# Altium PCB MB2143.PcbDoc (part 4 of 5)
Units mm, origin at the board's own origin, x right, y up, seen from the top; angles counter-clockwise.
Board outline 70 x 70 mm, 4 copper layers (Top Layer, Signal Layer 1, Signal Layer 2, Bottom Layer), stack 1.56 mm thick; 272 components, 188 nets, 1083 pads, 1158 vias.
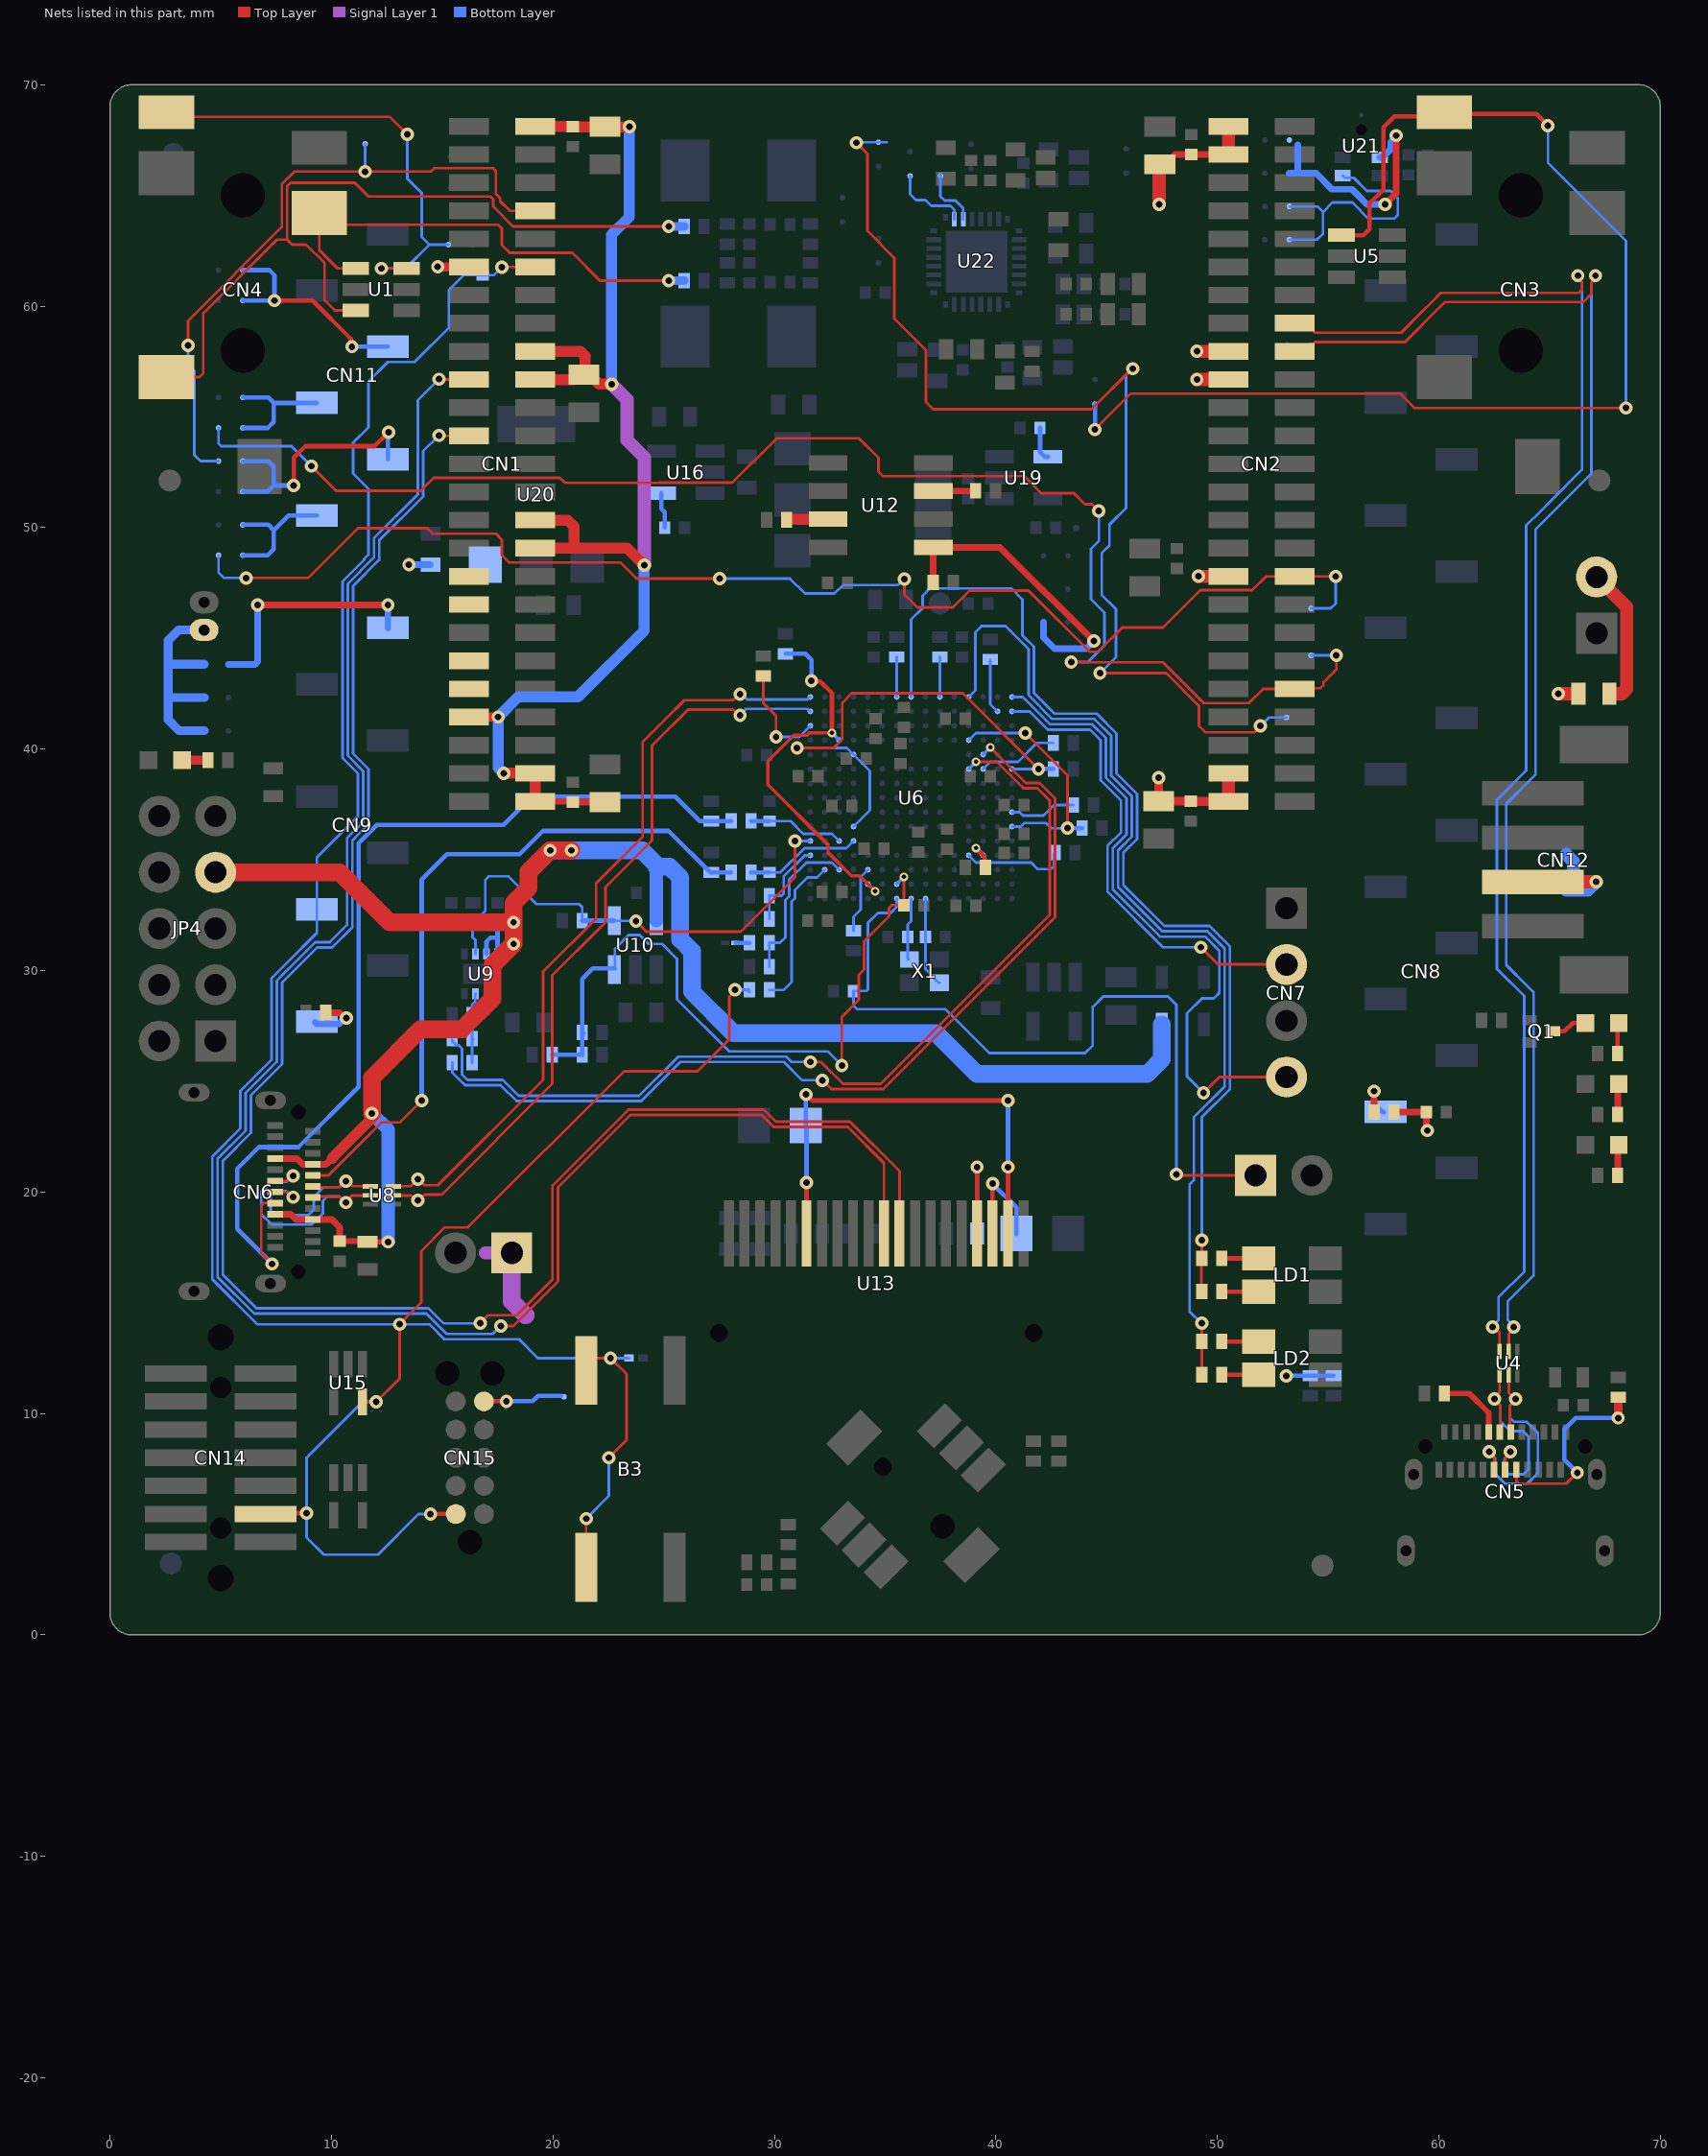
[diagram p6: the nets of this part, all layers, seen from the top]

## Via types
v1: diameter 0.6, hole 0.3, Top Layer to Bottom Layer, 1107 vias
v2: diameter 0.4, hole 0.2, Top Layer to Bottom Layer, tented both sides, 50 vias
v3: diameter 0.6, hole 0.3, Top Layer to Bottom Layer, tented both sides, 1 vias

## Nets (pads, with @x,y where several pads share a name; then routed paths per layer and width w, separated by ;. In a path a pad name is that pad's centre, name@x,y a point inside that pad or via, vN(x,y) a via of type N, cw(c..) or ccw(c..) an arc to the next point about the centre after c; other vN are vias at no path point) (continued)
NetC73_1: C73.1 U13.6 U13.19 | length 21.5
  Top Layer w0.2: v1(31.425,24.4) 31.444,24.4 31.719,24.125 v1(40.55,24.125) ; U13.6@31.45,18.125 v1(31.45,20.425) ; U13.19@40.55,18.125 v1(40.55,21.125)
  Bottom Layer w0.2: C73.1@31.425,23 v1(31.425,24.4) ; v1(31.45,20.425) C73.1@31.45,22.95 ; v1(40.55,21.125) v1(40.55,24.125)
NetC76_1: C76.1 U13.18 | length 5
  Top Layer w0.2: U13.18@39.85,18.125 v1(39.85,20.375)
  Bottom Layer w0.2: v1(39.85,20.375) 40.925,19.3 C76.1@40.925,18.125 C76.1@40.925,18.1
NetC79_1: C79.1 U16.4 | length 1.6
  Bottom Layer w0.2: U16.4@24.9,51.55 24.9,50.85 25.05,50.7 C79.1@25.05,50
NetC82_2: C82.2 U19.4 | length 1.5
  Bottom Layer w0.2: C82.2@42,54.506 42,53.4 42.2,53.2 U19.4@42.35,53.2
NetCN3_2: CN3.2 SB7.1 U5.1 | length 54.5
  Top Layer w0.12: v1(44.475,54.425) 46.1,56.05 58.25,56.05 58.9,55.4 v1(68.45,55.4)
  Top Layer w0.2: U5.1@55.6,63.2 56.6,63.2 56.875,63.475 56.875,64.635 57.5,65.26 57.5,68.075 57.999,68.574 60.074,68.574 CN3.2@60.25,68.75 60.326,68.674 64.401,68.674 v1(64.925,68.15)
  Bottom Layer w0.12: v1(64.925,68.15) 64.925,66.475 68.45,62.95 v1(68.45,55.4)
  Bottom Layer w0.2: v1(44.475,54.425) SB7.1@44.475,55.575
NetCN4_2: CN4.2 SB6.2 U1.6 | length 21.3
  Top Layer w0.12: CN4.2@2.55,68.75 2.75,68.55 12.625,68.55 v1(13.425,67.75) ; v1(12.25,61.7) U1.6@13.4,61.7
  Bottom Layer w0.12: v1(12.25,61.7) 13.35,61.7 14.425,62.775 ; v1(13.425,67.75) 13.425,65.75 14.075,65.1 14.075,63.125 14.425,62.775 ; SB6.2@15.275,62.775 14.425,62.775
NetCN4_4: CN4.4 R53.1 U1.1 | length 22
  Top Layer w0.12: U1.1@11.27,61.7 U1.1@11.1,61.7 10.275,61.7 9.45,62.525 CN4.4@9.45,64.2 9.975,63.675 17.525,63.675 17.7,63.5 17.7,62.75 18.05,62.4 20.875,62.4 22.125,61.15 v1(25.225,61.15)
  Bottom Layer w0.4: v1(25.225,61.15) R53.1@25.925,61.15
NetCN4_6: CN4.6 R45.1 U1.3 | length 36.4
  Top Layer w0.12: CN4.6@2.55,56.8 4.05,56.8 4.213,56.963 4.213,59.681 7.532,63 8,63 ; U1.3@11.1,59.8 10.15,59.8 9.693,60.257 9.693,61.943 8.86,62.776 8.224,62.776 8,63 ; v1(25.225,63.6) 18.2,63.6 17.3,64.5 17.3,64.825 17.175,64.95 11.675,64.95 11.055,65.57 8.163,65.57 8,65.408 8,63
  Bottom Layer w0.4: v1(25.225,63.6) R45.1@25.925,63.6
NetCN5_A5: CN5.A5 R6.2 | length 3.2
  Top Layer w0.25: R6.2@60.25,10.9 61.375,10.9 62.25,10.025 CN5.A5@62.25,9.16
NetCN5_B5: CN5.B5 R7.2 | length 9
  Top Layer w0.12: CN5.B5@63.5,7.46 63.5,6.94 63.61,6.83 65.755,6.83 v1(66.25,7.325)
  Top Layer w0.25: v1(68.095,9.795) v1@68.1,9.8
  Top Layer w0.4: v1@68.1,9.8 R7.2@68.1,10.725
  Bottom Layer w0.2: v1(66.25,7.325) 65.663,7.912 65.663,9.273 66.185,9.795 v1@67.845,9.795
NetCN6_A5: CN6.A5 R11.1 R13.2 | length 31.9
  Top Layer w0.12: CN6.A5@9.16,20.75 9.863,20.75 11.444,22.331 12.25,23.138 13.087,23.138 v1(14.075,24.125)
  Bottom Layer w0.2: v1(14.075,24.125) 14.075,34.1 15.22,35.245 18.495,35.245 19.55,36.3 25.223,36.3 R11.1@27.122,34.402 ; R11.1@27.15,34.43 R13.2@28.05,34.43
NetCN6_B5: CN6.B5 R14.2 R15.1 | length 44.6
  Top Layer w0.12: v1(7.325,16.75) 6.83,17.245 6.83,19.39 6.94,19.5 CN6.B5@7.46,19.5
  Bottom Layer w0.2: v1(7.325,16.75) 5.75,18.325 5.75,21.05 6.725,22.025 8.51,22.025 11.225,24.74 11.225,35.757 12.043,36.575 17.775,36.575 19.05,37.85 25.525,37.85 26.625,36.75 R14.2@28.05,36.75
NetCN8_8: CN8.8 R44.1 | length 2.1
  Top Layer w0.3: R44.1@57.075,23.602 v1(57.075,24.55)
  Bottom Layer w0.2: v1(57.075,24.55) 57.075,24.012 57.485,23.602 CN8.8@57.525,23.602
NetCN9_1: CN9.1 R43.1 | length 2.6
  Top Layer w0.3: R43.1@9.75,28.1 10.365,28.1 10.615,27.85 v1(10.675,27.85)
  Bottom Layer w0.3: CN9.1@9.267,27.666 9.35,27.583 10.329,27.583 10.571,27.825 v1@10.65,27.825 ; CN9.1@9.825,27.675 CN9.1@9.85,27.65
NetCN11_1: CN11.1 SB5.1 SB10.1 | length 6.1
  Bottom Layer w0.2: SB5.1@6,48.75 7.125,48.75 7.398,49.023 7.398,49.877 ; SB10.1@6,50.125 7.15,50.125 7.398,49.877 ; CN11.1@9.345,50.547 8.072,50.547 7.402,49.877 7.398,49.877
NetCN11_2: CN11.2 SB20.1 SB21.1 | length 12
  Top Layer w0.2: v1(8.3,51.9) 8.3,53.158 8.817,53.675 11.95,53.675 v1(12.575,54.3)
  Bottom Layer w0.2: SB21.1@6,51.625 7.125,51.625 7.398,51.898 ; SB20.1@6,53 7.15,53 7.398,52.752 7.398,51.898 ; v1(8.3,51.9) 8.298,51.898 7.398,51.898 ; CN11.2@12.55,53.087 12.55,54.275 v1(12.575,54.3)
NetCN11_3: CN11.3 SB23.1 SB25.1 | length 5.8
  Bottom Layer w0.2: SB23.1@6,54.5 7.125,54.5 7.398,54.773 7.398,55.627 ; SB25.1@6,55.875 7.15,55.875 7.398,55.627 ; CN11.3@9.345,55.627 7.398,55.627
NetCN11_4: CN11.4 SB28.1 SB30.1 | length 10.3
  Top Layer w0.2: v1(7.425,60.25) 9.15,60.25 10.871,58.529 10.871,58.221 v1(10.925,58.167)
  Bottom Layer w0.2: SB28.1@6,60.25 v1(7.425,60.25) 7.425,61.395 7.195,61.625 SB30.1@6,61.625 ; v1(10.925,58.167) CN11.4@12.55,58.167
NetCN12_3: CN12.3 SB33.1 SB34.1 | length 6
  Top Layer w0.6: CN12.3@64.25,34 v1(67.1,34)
  Bottom Layer w0.6: SB34.1@65.75,33.625 66.725,33.625 v1(67.1,34) ; SB33.1@65.75,35.25 66.075,34.925 66.075,33.75
NetCN15_5: CN15.5 SB1.1 | length 3.6
  Top Layer w0.2: CN15.5@16.885,10.54 16.895,10.55 v1(17.9,10.55)
  Bottom Layer w0.2: v1(17.9,10.55) 19.075,10.55 19.15,10.625 19.325,10.8 20.375,10.8
NetCN16_1: CN16.1 SB13.2 SB14.2 SB15.2 | length 10.6
  Bottom Layer w0.4: SB15.2@4.25,40.825 3.125,40.825 2.625,41.325 2.625,42.2 ; SB14.2@4.25,42.325 2.75,42.325 2.625,42.2 ; SB13.2@4.25,43.825 2.775,43.825 2.625,43.675 ; CN16.1@4.25,45.375 3.1,45.375 2.625,44.9 2.625,43.675 ; 2.625,42.2 2.625,43.675
NetJP3_2: JP3.2 R5.2 | length 6.5
  Top Layer w0.6: JP3.2@67.125,47.77 68.48,46.415 68.48,43.098 68.48,42.711 68.269,42.5 R5.2@67.7,42.5
NetLD1_1: LD1.1 R35.1 | length 1.6
  Top Layer w0.12: R35.1@50.3,15.475 R35.1@50.325,15.5
  Top Layer w0.2: R35.1@50.325,15.5 LD1.1@51.875,15.5
NetLD1_2: LD1.2 R36.1 | length 1.6
  Top Layer w0.12: R36.1@50.275,17.025 R36.1@50.3,17
  Top Layer w0.2: R36.1@50.3,17 LD1.2@51.875,17
NetLD2_1: LD2.1 R37.1 | length 1.6
  Top Layer w0.12: R37.1@50.275,11.825 R37.1@50.35,11.75
  Top Layer w0.2: R37.1@50.35,11.75 LD2.1@51.875,11.75
NetLD2_2: LD2.2 R38.2 | length 1.7
  Top Layer w0.12: R38.2@50.2,13.2 R38.2@50.25,13.25
  Top Layer w0.2: R38.2@50.25,13.25 LD2.2@51.875,13.25
NetLD3_1: LD3.1 R41.2 | length 1.4
  Top Layer w0.2: R41.2@68.075,26.275 68.075,27.575 LD3.1@68.125,27.625
NetLD3_2: LD3.2 Q1.3 | length 1.6
  Top Layer w0.2: Q1.3@65.225,27.25 65.675,27.25 66.05,27.625 LD3.2@66.625,27.625
NetLD4_1: LD4.1 R48.1 | length 1.2
  Top Layer w0.4: LD4.1@3.25,39.5 R48.1@4.425,39.5
NetLD5_1: LD5.1 R62.2 | length 1.4
  Top Layer w0.3: R62.2@68.075,20.75 68.075,22.075 LD5.1@68.125,22.125
NetLD6_1: LD6.1 R61.2 | length 1.4
  Top Layer w0.3: R61.2@68.075,23.5 68.075,24.825 LD6.1@68.125,24.875
NetR12_1: R12.1 U6.F15 | length 1.8
  Bottom Layer w0.12: U6.F15@37.475,42.35 R12.1@37.475,44.15
NetR24_1: R24.1 U6.P3 | length 7.1
  Bottom Layer w0.12: R24.1@29.775,29.125 30.425,29.125 30.775,29.475 30.775,33.111 30.925,33.261 30.925,33.631 31.499,34.205 31.93,34.205 U6.P3@32.275,34.55
NetR25_1: R25.1 U6.J15 | length 1.8
  Bottom Layer w0.12: U6.J15@35.525,42.35 R25.1@35.525,44.15
NetR28_1: R28.1 U6.D4 | length 4.8
  Bottom Layer w0.12: U6.D4@38.775,35.2 39.1,34.875 41.6,34.875 41.9,34.575 42.475,34.575 42.625,34.725 42.625,35.275 R28.1@42.675,35.325
NetR31_1: R31.1 R32.1 R33.1 U9.7 | length 3.2
  Bottom Layer w0.12: R32.1@16.35,25.825 R32.1@16.35,25.845 R31.1@16.35,26.92 ; R33.1@16.35,27.995 16.35,26.95 R31.1@16.4,26.9 ; R33.1@16.35,28 16.355,28.005 16.355,28.455 16.49,28.59 16.49,28.94 U9.7@16.5,28.95
NetR46_2: R46.2 U13.17 | length 6
  Top Layer w0.2: U13.17@39.15,18.125 v1(39.15,21.125)
  Bottom Layer w0.2: v1(39.15,21.125) 39.15,18.2 R46.2@39.175,18.175
NetR57_1: R57.1 U6.B14 | length 2.4
  Bottom Layer w0.12: R57.1@39.75,44 39.75,42.025 U6.B14@40.075,41.7
NetR58_1: R58.1 U6.R13 | length 4.7
  Top Layer w0.12: R58.1@29.5,43.3 29.5,42.075 30.075,41.5 v1(30.075,40.55)
  Bottom Layer w0.12: v1(30.075,40.55) 31.125,40.55 U6.R13@31.625,41.05
NetR59_2: R59.2 SB38.1 U12.1 | length 13.9
  Top Layer w0.3: R59.2@37.175,47.525 U12.1@37.175,49.11 40.19,49.11 v1(44.425,44.875)
  Bottom Layer w0.3: SB38.1@42.15,45.725 42.15,45.025 42.65,44.525 44.075,44.525 v1(44.425,44.875)
NetR60_1: R60.1 U12.3 | length 1.9
  Top Layer w0.3: U12.3@37.175,51.65 39.073,51.65 R60.1@39.088,51.665
NetR63_2: R63.2 U12.7 | length 1.9
  Top Layer w0.3: R63.2@30.55,50.353 R63.2@30.578,50.38
  Top Layer w0.5: R63.2@30.578,50.38 U12.7@32.425,50.38
NetR64_1: R64.1 U6.C4 | length 1.5
  Top Layer w0.2: v2(39.1,35.525) 39.499,35.126 39.499,34.676 R64.1@39.525,34.65
  Bottom Layer w0.2: v2(39.1,35.525) U6.C4@39.425,35.2
NetSB3_1: SB3.1 SB12.1 U21.1 | length 11.8
  Bottom Layer w0.12: SB12.1@53.25,63 54.5,63 54.775,63.275 54.775,64.25 ; SB3.1@53.25,64.5 54.525,64.5 54.775,64.25 ; U21.1@55.662,65.886 55.751,65.797 56.159,65.797 56.756,65.2 57.825,65.2 58.151,64.874 58.151,64.113 57.988,63.95 56.825,63.95 56.1,64.675 55.2,64.675 54.775,64.25
NetSB4_1: SB4.1 SB11.1 U21.4 | length 10.8
  Top Layer w0.3: v1(57.575,64.6) 58.075,65.1 v1(58.075,67.7)
  Bottom Layer w0.3: SB4.1@53.25,66 53.625,66 54.45,66 55.175,65.275 56.087,65.275 56.762,64.6 v1(57.575,64.6) ; 53.625,66.075 53.625,67.275 ; U21.4@57.338,66.708 57.439,66.708 57.825,67.094 57.825,67.39 58.075,67.64 v1(58.075,67.7)
NetSB16_1: SB16.1 U22.2 | length 3.5
  Bottom Layer w0.12: SB16.1@36.125,65.875 36.125,65.05 36.39,64.785 36.823,64.785 37.083,64.525 37.95,64.525 38.125,64.35 U22.2@38.125,63.925
NetSB17_1: SB17.1 U22.3 | length 2.7
  Bottom Layer w0.12: SB17.1@37.5,65.925 37.5,64.95 37.685,64.765 38.175,64.765 38.525,64.415 U22.3@38.525,63.925
NetSB32_2: SB32.2 SB35.1 | length 49.8
  Top Layer w0.12: v1(33.7,67.375) 34.198,66.877 34.198,63.395 35.42,62.173 35.42,59.43 36.848,58.002 36.848,55.673 37.176,55.345 44.32,55.345 46.15,57.175 v1(46.175,57.175) ; v1(44.7,43.425) 47.696,43.425 49.175,41.946 49.175,41.05 49.475,40.75 51.65,40.75 v1(51.95,41.05)
  Bottom Layer w0.12: v1(33.7,67.375) 33.725,67.4 SB32.2@34.7,67.4 35.075,67.4 ; v1(44.7,43.425) 45.425,44.15 45.425,46.32 44.78,46.965 44.78,47.885 ; 44.78,47.904 44.78,48.843 45.13,49.193 45.13,50.134 45.88,50.884 45.88,56.88 v1(46.175,57.175) ; v1(51.95,41.05) 52.325,41.425 SB35.1@53.125,41.425
NRST: B3.1 B3.2 C15.2 CN1.12 CN9.3 CN14.12 CN15.10 R24.2 U3.1 U15.5 | length 132.7
  Top Layer w0.12: U15.5@11.45,10.525 v1(12.025,10.525) 13.075,11.575 v1(13.075,14.025) 14.05,15 14.05,17.325 15.125,18.4 16.164,18.4 23.214,25.45 26.525,25.45 27.965,26.89 27.965,28.815 28.22,29.07 v1(28.22,29.125) ; v1@17.705,61.765 CN1.12@19.21,61.765 ; B3.1@21.5,3.025 B3.1@21.5,3.05 v1(21.5,5.25) ; B3.2@21.7,12.525 21.725,12.5 v1(22.6,12.5) 23.325,11.775 23.325,8.8 v1(22.525,8)
  Top Layer w0.2: CN14.12@7.95,5.475 7.975,5.5 v1(8.875,5.5) ; v1(14.475,5.45) 14.49,5.465 CN15.10@15.62,5.465
  Bottom Layer w0.12: 11.464,48.561 11.677,48.773 11.677,51.747 10.985,52.439 10.985,53.836 11.677,54.528 11.677,56.602 12.552,57.477 13.756,57.477 15.305,59.026 15.305,60.73 15.975,61.4 C15.2@16.825,61.4 17.34,61.4 v1(17.695,61.755) ; 11.48,48.545 10.497,47.561 10.497,39.598 11.197,38.898 11.197,36.964 9.345,35.112 CN9.3@9.345,32.767 9.345,31.696 7.966,30.318 7.295,29.647 7.295,25.974 5.89,24.569 5.89,22.869 4.62,21.599 4.62,16.059 6.654,14.025 v1(13.075,14.025) 14.425,14.025 15.1,13.35 18.475,13.35 19.325,12.5 v1(22.6,12.5) U3.1@23.438,12.5 ; v1(12.025,10.525) 11.4,10.525 8.875,8 v1(8.875,5.5) 8.875,4.4 9.65,3.625 12.1,3.625 13.925,5.45 v1(14.475,5.45) ; v1(21.5,5.25) 22.525,6.275 v1(22.525,8) ; R24.2@28.85,29.05 R24.2@28.875,29.025
  Bottom Layer w0.15: v1(28.22,29.125) R24.2@28.85,29.125
OLED.CS: CN1.19 U13.11 | length 88.8
  Top Layer w0.12: v1(14.85,56.7) 14.865,56.685 CN1.19@16.21,56.685 ; v1(17.65,13.95) 18.214,13.95 20.225,15.961 20.225,20.2 23.505,23.48 29.425,23.48 29.967,22.938 33.312,22.938 34.95,21.3 U13.11@34.95,18.125
  Bottom Layer w0.12: v1(14.85,56.7) 13.9,55.75 13.9,51.5 11.917,49.517 11.917,48.642 10.737,47.462 10.737,39.698 11.437,38.998 11.437,36.704 10.705,35.972 10.705,32.055 9.925,31.275 9.263,31.275 8.049,30.061 7.894,29.906 7.535,29.548 7.535,25.875 6.13,24.47 6.13,22.769 4.86,21.499 4.86,16.158 6.513,14.505 14.284,14.505 15.199,13.59 17.29,13.59 v1(17.65,13.95)
OLED.RST: CN1.23 U13.12 | length 86.2
  Top Layer w0.12: v1(14.85,54.16) 14.865,54.145 CN1.23@16.21,54.145 ; v1(16.725,14.07) 16.725,14.1 17.055,14.43 18.355,14.43 19.985,16.06 19.985,20.299 23.406,23.72 29.524,23.72 30.067,23.178 33.412,23.178 35.65,20.939 U13.12@35.65,18.125
  Bottom Layer w0.12: v1(14.85,54.16) 14.14,53.45 14.14,51.401 12.157,49.418 12.157,48.543 10.977,47.363 10.977,39.797 11.677,39.097 11.677,36.605 11.199,36.126 10.945,35.873 10.945,31.956 10.024,31.035 9.362,31.035 7.775,29.448 7.775,25.775 6.37,24.37 6.37,22.67 5.1,21.4 5.1,16.258 6.613,14.745 14.384,14.745 15.059,14.07 v1(16.725,14.07)
OSC32_IN: CN1.33
OSC32_OUT: CN1.35
OSC_IN: CN1.39
OSC_OUT: CN1.41
STLK_LED: R37.2 R38.1 U6.D15 | length 46.1
  Top Layer w0.12: v1(49.3,14.075) R38.1@49.3,13.25 49.3,11.775 R37.2@49.325,11.75
  Bottom Layer w0.12: U6.D15@38.775,42.35 39.075,42.65 39.075,45.275 39.35,45.55 40.439,45.55 41.475,44.514 41.475,42.429 42.547,41.357 44.451,41.357 45.205,40.603 45.205,38.803 46.135,37.873 46.135,36.041 45.52,35.426 45.52,33.763 47.513,31.77 49.548,31.77 50.33,30.988 50.33,24.751 48.94,23.361 48.94,20.529 48.75,20.339 48.75,14.6 v1@49.275,14.075
STLK_NRST: C41.2 JP1.1 U6.J1 | length 35.2
  Top Layer w0.12: v1(48.15,20.8) 48.2,20.75 JP1.1@51.73,20.75
  Bottom Layer w0.12: U6.J1@35.525,33.25 35.525,32.875 35.25,32.6 34.675,32.6 34.229,32.154 34.229,29.145 34.159,29.075 C41.2@33.575,29.075 33.575,28.425 33.75,28.25 37.725,28.25 39.7,26.275 44.025,26.275 44.375,26.625 44.375,28.35 44.85,28.825 47.775,28.825 48.15,28.45 v1(48.15,20.8)
STLK_OSC_IN: C39.2 U6.G1 X1.1 | length 4.1
  Bottom Layer w0.12: U6.G1@36.825,33.25 C39.2@36.825,31.52 36.825,30.07 36.95,29.945 36.955,29.945 37.085,29.815 37.085,29.765 37.4,29.45 X1.1@37.45,29.45
STLK_OSC_OUT: C40.1 U6.H1 X1.3 | length 2.8
  Bottom Layer w0.12: X1.3@36.05,30.5 36.025,30.525 36.025,30.575 C40.1@36.025,31.52 36.025,32.075 36.175,32.225 U6.H1@36.175,33.25
STLK_SWCLK: CN7.2 U6.A14 | length 21.5
  Top Layer w0.12: v1(49.25,31.05) 50.025,30.275 CN7.2@53.175,30.275
  Bottom Layer w0.12: U6.A14@40.725,41.7 41.525,41.7 42.348,40.877 44.252,40.877 44.725,40.404 44.725,38.604 45.655,37.674 45.655,36.24 45.04,35.625 45.04,33.564 47.554,31.05 v1(49.25,31.05)
STLK_SWDIO: CN7.4 U6.A15 | length 30.1
  Top Layer w0.12: v1(49.375,24.475) 50.09,25.19 CN7.4@53.125,25.19
  Bottom Layer w0.12: U6.A15@40.725,42.35 41.214,42.35 42.447,41.117 44.351,41.117 44.965,40.503 44.965,38.703 45.895,37.773 45.895,36.141 45.28,35.526 45.28,33.663 47.413,31.53 49.449,31.53 50.09,30.889 50.09,28.991 49.844,28.745 49.309,28.745 48.63,28.066 48.63,25.22 v1(49.375,24.475)
STLK_UCPD_CC1_C: C37.1 R13.1 U6.M5 | length 5.2
  Bottom Layer w0.12: 30.235,34.43 30.266,34.43 31.361,35.525 33.25,35.525 U6.M5@33.575,35.85
  Bottom Layer w0.125: C37.1@29.775,34.43 30.235,34.43
  Bottom Layer w0.2: R13.1@28.95,34.43 C37.1@29.775,34.43
STLK_UCPD_CC2_C: C38.1 R14.1 U6.N5 | length 4.3
  Bottom Layer w0.12: C38.1@29.775,36.75 30.725,36.75 31.3,36.175 32.6,36.175 U6.N5@32.925,35.85
  Bottom Layer w0.2: R14.1@28.95,36.75 C38.1@29.775,36.75
STLK_USB_CN_N: CN6.A7 CN6.B7 U8.2 | length 11.5
  Top Layer w0.12: CN6.B7@7.46,20.5 7.966,20.5 8.191,20.725 v1(8.275,20.725) ; CN6.A7@9.16,19.75 9.205,19.795 10.346,19.795 10.616,19.525 v1(10.655,19.525) 10.655,19.571 10.924,19.84 U8.2@11.755,19.84
  Bottom Layer w0.12: v1(8.275,20.725) 8.236,20.725 7.966,20.455 7.276,20.455 6.83,20.009 6.83,19.001 7.301,18.53 9.124,18.53 9.445,18.851 9.62,19.026 9.62,19.6 9.815,19.795 10.346,19.795 10.616,19.525 v1(10.655,19.525)
STLK_USB_CN_P: CN6.A6 CN6.B6 U8.1 | length 10.2
  Top Layer w0.12: CN6.B6@7.46,20 7.966,20 8.201,19.765 v1(8.275,19.765) ; CN6.A6@9.077,20.333 CN6.A6@9.16,20.25 9.195,20.215 10.346,20.215 10.616,20.485 v1(10.655,20.485) 10.74,20.485 10.965,20.26 U8.1@11.755,20.26
  Bottom Layer w0.12: v1(8.275,19.765) 8.236,19.765 7.966,20.035 7.45,20.035 7.25,19.835 7.25,19.175 7.475,18.95 8.95,18.95 9.025,19.025 9.2,19.2 9.2,19.774 9.641,20.215 10.346,20.215 10.616,20.485 v1(10.655,20.485)
STLK_USB_N: U6.R14 U8.5 | length 34.7
  Top Layer w0.12: U8.5@12.805,19.84 13.595,19.84 13.82,19.615 v1(13.905,19.615) 13.944,19.615 14.214,19.885 14.979,19.885 19.975,24.881 19.975,29.775 22.124,31.924 22.37,32.17 22.37,33.77 24.475,35.875 24.475,40.15 24.655,40.33 26.11,41.785 28.141,41.785 28.411,41.515 v1(28.45,41.515)
  Bottom Layer w0.12: v1(28.45,41.515) 28.45,41.536 28.729,41.815 31.49,41.815 31.605,41.7 U6.R14@31.625,41.7
STLK_USB_P: U6.R15 U8.6 | length 34.7
  Top Layer w0.12: U8.6@12.805,20.26 13.575,20.26 13.89,20.575 v1(13.905,20.575) 13.944,20.575 14.214,20.305 14.805,20.305 19.555,25.055 19.555,29.949 21.95,32.344 21.95,33.944 24.055,36.049 24.055,40.324 24.481,40.75 25.078,41.347 25.936,42.205 28.141,42.205 28.411,42.475 v1(28.45,42.475)
  Bottom Layer w0.12: v1(28.45,42.475) 28.52,42.475 28.76,42.235 31.49,42.235 31.605,42.35 U6.R15@31.625,42.35
STLK_VCP_RX: R20.1 U6.C10 | length 3.7
  Bottom Layer w0.12: U6.C10@39.425,39.1 39.75,39.425 41,39.425 41.85,40.275 41.937,40.275 R20.1@42.6,40.275
STLK_VCP_TX: R21.1 U6.A7 | length 3
  Bottom Layer w0.12: U6.A7@40.725,37.15 41.075,37.15 41.23,36.995 42.149,36.995 42.629,37.475 43.065,37.475 R21.1@43.5,37.475
T_JTDI: R19.1 U6.L3 | length 3
  Bottom Layer w0.12: R19.1@33.575,31.8 33.575,32.425 33.9,32.75 33.9,34.225 U6.L3@34.225,34.55
T_PWR_EN: R34.2 R40.2 U6.R5 U9.2 U10.4 | length 22.3
  Top Layer w0.12: v1(23.75,32.225) 24.225,31.75 28.475,31.75 30.925,34.2 v1(30.925,35.85)
  Bottom Layer w0.12: R34.2@16.375,32.025 16.375,31.5 16.5,31.375 U9.2@16.5,30.75 ; R34.2@16.4,32.15 16.495,32.15 16.69,32.345 16.69,32.44 16.95,32.7 16.95,34.1 17.1,34.25 18,34.25 19.25,33 21.175,33 21.325,32.85 R40.2@21.325,32.25 ; U10.4@22.79,32.24 23.735,32.24 v1(23.75,32.225) ; v1(30.925,35.85) U6.R5@31.625,35.85
  Bottom Layer w0.2: R40.2@21.32,32.25 U10.4@22.775,32.25
T_PWR_EXT: R22.1 R23.1 U6.R4 | length 4.1
  Bottom Layer w0.12: R23.1@29.775,32.325 R22.1@29.775,33.375 30.325,33.375 30.418,33.467 30.418,34.242 31.375,35.2 U6.R4@31.625,35.2
T_PWR_INT: C95.1 R29.2 R30.2 R39.2 U6.J2 U10.3 | length 31.8
  Top Layer w0.12: v1(33.046,25.711) 33.046,27.906 33.815,28.676 33.815,29.806 34.055,30.046 34.055,31.316 35.181,32.441 35.181,32.825 35.306,32.95 C95.1@35.85,32.95 v2(35.85,34.225)
  Bottom Layer w0.12: R30.2@21.325,26.175 R30.2@21.325,26.195 ; U10.3@22.8,30.1 22.8,30.975 23.425,31.6 23.924,31.6 24.324,31.2 24.925,31.2 25.6,30.525 25.6,28.7 27.95,26.35 32.407,26.35 v1(33.046,25.711)
  Bottom Layer w0.15: U6.J2@35.525,33.9 v2(35.85,34.225)
  Bottom Layer w0.2: R29.2@19.975,26.195 21.305,26.195 R30.2@21.325,26.175 ; R30.2@21.325,26.195 21.325,27.125 R39.2@21.375,27.175 ; R39.2@21.325,27.2 21.325,29.625 21.8,30.1 U10.3@22.8,30.1
T_PWR_LED: R35.2 R36.2 U6.H15 | length 48.1
  Top Layer w0.12: R36.2@49.275,16.975 49.275,15.525 R35.2@49.3,15.5 ; R36.2@49.3,17 v1(49.3,17.825)
  Bottom Layer w0.12: U6.H15@36.175,42.35 36.175,43.57 36.178,43.573 ; 36.175,43.575 36.175,45.85 36.687,46.363 36.687,46.913 37.03,47.255 40.695,47.255 41.2,46.75 41.2,45.129 41.715,44.614 41.715,42.528 42.646,41.597 44.55,41.597 45.445,40.702 45.445,38.902 46.375,37.972 46.375,35.942 45.76,35.327 45.76,33.862 47.612,32.01 49.648,32.01 50.57,31.088 50.57,24.652 49.3,23.382 v1(49.3,17.825)
T_PWR_SEL1: R31.2 U6.D10 | length 42.9
  Top Layer w0.12: v1(31.625,25.87) 32.105,25.87 33.09,24.885 34.81,24.885 42.435,32.51 42.435,37.676 41.877,38.234 41.252,38.234 41.012,38.474 41.001,38.474 40.05,39.425 v2(39.1,39.425)
  Bottom Layer w0.12: R31.2@15.45,26.92 15.45,26.825 15.645,26.63 15.74,26.63 15.9,26.47 15.9,25.3 16.138,25.063 17.738,25.063 18.46,24.34 23.89,24.34 25.66,26.11 30.54,26.11 30.78,25.87 v1(31.625,25.87)
  Bottom Layer w0.15: U6.D10@38.775,39.1 v2(39.1,39.425)
T_PWR_SEL2: R32.2 U6.C11 | length 42.4
  Top Layer w0.12: v1(32.171,25.043) 32.569,24.645 34.909,24.645 42.675,32.411 42.675,37.775 41.977,38.474 41.351,38.474 v2(39.75,40.075)
  Bottom Layer w0.12: R32.2@15.45,25.845 15.465,25.83 15.465,25.385 15.762,25.088 15.773,25.088 16.038,24.823 17.638,24.823 18.361,24.1 23.989,24.1 25.759,25.87 30.43,25.87 31.257,25.043 v1(32.171,25.043)
  Bottom Layer w0.15: U6.C11@39.425,39.75 v2(39.75,40.075)
T_SWCLK: R18.1 U6.A10 U6.M6 U6.M11 | length 22.7
  Top Layer w0.12: v1(31.025,40.05) 32.675,40.05 33.067,40.442 33.067,42.092 33.495,42.52 38.505,42.52 v1(41.925,39.1)
  Bottom Layer w0.12: v1(31.025,40.05) 31.57,40.05 31.575,40.055 33.27,40.055 U6.M11@33.575,39.75 34.313,39.012 34.313,37.238 U6.M6@33.575,36.5 ; U6.A10@40.725,39.1 v1(41.925,39.1)
  Bottom Layer w0.2: v1(41.925,39.1) R18.1@42.6,39.1
T_SWDIO: R16.1 U6.L2 U6.N12 | length 17.6
  Top Layer w0.15: v2(32.6,40.725) 31.575,40.725 31.48,40.63 30.88,40.63 29.7,39.45 29.7,38.4 32.425,35.675 32.425,35.325 33.475,34.275 33.85,34.275 v2(34.55,33.575)
  Top Layer w0.2: v1(31.675,43.075) 31.693,43.057 32.072,43.057 32.6,42.529 v2(32.6,40.725)
  Bottom Layer w0.15: v2(32.6,40.725) U6.N12@32.925,40.4 ; U6.L2@34.225,33.9 v2(34.55,33.575)
  Bottom Layer w0.2: R16.1@30.5,44.3 31.4,44.3 31.675,44.025 v1(31.675,43.075)
T_SWO: R17.1 U6.A6 U6.D12 | length 11.1
  Top Layer w0.12: v1(41.325,40.725) 43.23,38.82 v1(43.23,36.425)
  Bottom Layer w0.12: U6.D12@38.775,40.4 39.1,40.725 v1(41.325,40.725) ; U6.A6@40.725,36.5 41.125,36.5 41.28,36.655 42.27,36.655 42.5,36.425 v1(43.23,36.425)
  Bottom Layer w0.2: v1(43.23,36.425) R17.1@43.9,36.425
T_VCC: LNK1.2 R26.2 | length 0.6
  Bottom Layer w0.2: LNK1.2@28.25,31.25 R26.2@28.875,31.25
T_VCC_AIN: R26.1 R27.1 U6.N3 | length 7.3
  Bottom Layer w0.12: R27.1@29.775,30.175 R26.1@29.775,31.25 30.25,31.25 30.5,31.5 30.5,33.175 30.675,33.35 30.675,34.107 31.443,34.875 32.6,34.875 U6.N3@32.925,34.55
USB_C_N: CN5.A7 CN5.B7 U4.2 | length 11.5
  Top Layer w0.12: v1(62.275,8.275) 62.275,8.191 62.5,7.966 CN5.B7@62.5,7.46 ; U4.2@63.16,11.75 63.16,10.919 63.429,10.65 63.475,10.65 63.475,10.611 63.205,10.341 63.205,9.2 CN5.A7@63.25,9.155
  Bottom Layer w0.12: v1(62.275,8.275) 62.275,8.236 62.545,7.966 62.545,7.276 62.991,6.83 63.999,6.83 64.47,7.301 64.47,9.124 64.149,9.445 63.974,9.62 63.4,9.62 63.205,9.815 63.205,10.346 63.475,10.616 v1(63.475,10.655)
USB_C_P: CN5.A6 CN5.B6 U4.1 | length 10.1
  Top Layer w0.12: U4.1@62.74,11.75 62.74,10.96 62.515,10.735 v1(62.515,10.655) 62.515,10.611 62.785,10.341 62.785,9.19 CN5.A6@62.75,9.155 ; CN5.B6@63,7.46 63,7.966 63.235,8.201 v1(63.235,8.275)
  Bottom Layer w0.12: v1(62.515,10.655) 62.515,10.616 62.785,10.346 62.785,9.641 63.226,9.2 63.8,9.2 63.975,9.025 64.05,8.95 64.05,7.475 63.825,7.25 63.165,7.25 62.965,7.45 62.965,7.966 63.235,8.236 v1(63.235,8.275)
USB_HS_N: CN2.18 U4.5 | length 66.9
  Top Layer w0.12: CN2.18@53.5,57.955 54.025,57.955 54.34,58.27 54.34,58.31 54.41,58.38 58.474,58.38 60.073,59.979 60.274,60.18 66.514,60.18 66.885,60.551 66.885,61.065 67.075,61.255 v1(67.075,61.375) ; U4.5@63.16,12.8 63.16,13.595 63.385,13.82 v1(63.385,13.905) v1@63.385,13.944
  Bottom Layer w0.12: v1(63.385,13.905) 63.385,13.944 63.115,14.214 63.115,15.065 64.275,16.225 64.275,29.019 64.029,29.265 63.045,30.249 63.045,37.526 64.124,38.605 64.37,38.851 64.37,49.92 64.782,50.332 66.172,51.722 66.885,52.435 66.885,61.065 67.075,61.255 v1(67.075,61.375)
USB_HS_P: CN2.16 U4.6 | length 66.2
  Top Layer w0.12: CN2.16@53.5,59.225 54.025,59.225 54.34,58.91 54.34,58.87 54.41,58.8 58.3,58.8 59.278,59.778 59.653,60.153 60.1,60.6 66.34,60.6 66.465,60.725 66.465,61.065 66.275,61.255 v1(66.275,61.375) ; v1@62.425,13.944 v1(62.425,13.905) 62.471,13.905 62.74,13.636 U4.6@62.74,12.8
  Bottom Layer w0.12: v1(62.425,13.905) 62.425,13.944 62.695,14.214 62.695,15.239 63.855,16.399 63.855,28.845 62.625,30.075 62.625,37.7 63.95,39.025 63.95,50.094 64.608,50.752 65.028,51.172 66.465,52.609 66.465,61.065 66.275,61.255 v1(66.275,61.375)
VBAT: C1.1 C2.2 C3.2 C4.2 C6.2 C7.2 C8.1 C9.2 C11.2 C69.1 CN1.2 CN1.11 CN1.18 CN1.20 CN1.30 CN1.32 CN1.43 CN1.48 CN1.50 CN2.1 CN2.3 CN2.17 CN2.19 CN2.33 CN2.47 CN2.49 JP2.1 R5.1 R8.2 R9.2 R44.2 | length 88.3
  Top Layer w0.3: CN1.50@19.21,37.635 20.865,37.635 C8.1@20.9,37.6 C3.2@22.35,37.6 ; C4.2@47.591,66.35 48.086,66.845 C9.2@48.815,66.845 CN2.3@50.5,66.845 ; CN2.1@50.485,68.1 CN2.1@50.5,68.115 ; R44.2@57.975,23.602 R44.2@58.027,23.602 ; R44.2@58,23.575 R44.2@58.027,23.602 ; v1(59.475,22.775) 59.44,22.81 C69.1@59.44,23.602 R44.2@58.027,23.602
  Top Layer w0.4: v1(14.8,61.775) 14.81,61.765 CN1.11@16.21,61.765 ; CN1.43@16.21,41.445 v1(17.53,41.445) ; C6.2@47.175,37.75 47.275,37.65 C11.2@48.8,37.65 ; C6.2@47.35,37.65 v1(47.35,38.7) ; C11.2@48.8,37.675 C11.2@48.84,37.635 ; C11.2@48.875,37.6 C11.2@48.84,37.635 ; CN2.49@50.5,37.635 C11.2@48.84,37.635
  Top Layer w0.5: v1(17.775,38.905) CN1.48@19.21,38.905 CN1.50@19.21,37.635 ; CN1.32@19.21,49.065 20.95,49.065 ; CN1.30@19.21,50.335 20.665,50.335 20.95,50.05 20.95,49.065 ; CN1.20@19.21,56.685 20.935,56.685 21.2,56.95 21.45,56.95 21.45,57.75 21.245,57.955 CN1.18@19.21,57.955 ; CN1.2@19.21,68.115 20.885,68.115 C7.2@20.9,68.1 C2.2@22.5,68.1 ; C1.1@21.4,56.9 21.65,56.9 22.075,56.475 v1(22.65,56.475) ; C2.2@22.35,68.1 C2.2@22.5,68.1 ; v1(23.45,68.1) C2.2@22.5,68.1 ; v1@24.106,48.319 23.36,49.065 20.95,49.065
  Top Layer w0.6: v1(47.375,64.6) C4.2@47.375,66.4 ; v1(49.075,56.69) 49.08,56.685 CN2.19@50.5,56.685 ; v1(49.075,57.96) 49.08,57.955 CN2.17@50.5,57.955 ; v1(49.15,47.8) 49.155,47.795 CN2.33@50.5,47.795 ; CN2.49@50.5,37.635 CN2.47@50.5,38.905 ; CN2.3@50.5,66.845 CN2.1@50.5,68.115 ; v1(65.4,42.5) R5.1@66.3,42.5
  Signal Layer 1 w0.6: 16.95,17.25 JP2.1@18.145,17.25 ; v1(22.65,56.475) 23.345,55.78 23.345,53.945 24.125,53.165 v1(24.125,48.3)
  Signal Layer 1 w0.8: JP2.1@18.145,17.25 18.145,15.055 18.775,14.425
  Bottom Layer w0.2: v1(53.12,11.7) R9.2@54.2,11.7 R8.2@55.25,11.7
  Bottom Layer w0.5: v1(17.775,38.905) 17.53,39.15 v1(17.53,41.445) 18.435,42.35 21.125,42.35 24.125,45.35 v1(24.125,48.3) ; v1(22.65,56.475) 22.65,63.225 23.455,64.03 23.455,68.095 v1(23.45,68.1)
VBUS_STLK: C35.1 C44.2 C46.2 CN6.A4 CN6.A9 CN6.B4 CN6.B9 D1.1 JP4.7 U7.1 U9.3 U9.4 U10.5 | length 91.2
  Top Layer w0.25: C35.1@10.375,17.775 11.6,17.775 U7.1@11.625,17.75 12.55,17.75 v1(12.555,17.745) v1@12.678,17.745 ; 10.375,18.395 10.38,18.4
  Top Layer w0.3: CN6.B4@7.46,19 8.163,19 8.413,18.75 CN6.A9@9.16,18.75 10.03,18.75 10.38,18.4 ; CN6.B9@7.46,21.5 8.45,21.5 8.7,21.25 8.872,21.25 CN6.A4@9.16,21.25 9.755,21.25 10.03,21.525 ; C35.1@10.375,17.775 10.375,18.395
  Top Layer w0.5: 10.03,21.525 11.806,23.301 11.806,23.531 v1(11.825,23.55)
  Top Layer w0.8: JP4.7@4.77,34.435 10.365,34.435 12.625,32.175 v1(18.225,32.175) ; v1(11.825,23.55) 11.825,25.15 14.025,27.35 15.9,27.35 17.275,28.725 17.275,30.25 v1(18.225,31.2) v1(18.225,32.175) ; v1(19.875,35.425) 18.9,34.45 18.9,33.725 18.225,33.05 v1(18.225,32.175) ; v1@19.925,35.425 v1(20.835,35.425)
  Bottom Layer w0.2: U9.3@17,30.75 17,31.3 17.175,31.475 17.5,31.475 ; U9.4@17.5,30.75 17.5,31.475 ; v1(18.225,32.175) 18.2,32.15 C44.2@17.5,32.15 17.5,31.475
  Bottom Layer w0.6: v1(11.825,23.55) 12.555,22.82 v1(12.555,17.745) ; U10.5@24.675,32.25 24.675,34.39
  Bottom Layer w0.8: v1(19.875,35.425) v1(20.835,35.425) 24.025,35.425 24.675,34.775 24.675,34.69 25.26,34.69 25.75,34.2 25.75,31.4 26.275,30.875 26.275,29.05 28.15,27.175 37.3,27.175 39.15,25.325 46.825,25.325 47.5,26 D1.1@47.5,27.555
VIN: C83.2 CN9.8 SB13.1 U20.3 | length 11.8
  Top Layer w0.3: v1(6.675,46.5) v1(12.55,46.5)
  Bottom Layer w0.3: SB13.1@5.35,43.825 6.55,43.825 6.675,43.95 v1(6.675,46.5) ; CN9.8@12.55,45.467 v1(12.55,46.5) ; v1(13.5,48.325) C83.2@14.475,48.325
WIFI.PTA_GRA: CN2.34 SB5.2 SB40.2 | length 60.4
  Top Layer w0.12: v1(6.15,47.725) 8.95,47.725 11.2,49.975 14.325,49.975 14.575,49.725 17.425,49.725 17.7,49.45 17.7,48.75 18.025,48.425 23.05,48.425 23.775,47.7 v1(27.525,47.7) ; v1(35.875,47.675) 35.875,46.975 36.455,46.395 38.062,46.395 38.817,47.15 41.471,47.15 44.226,44.395 44.624,44.395 45.714,45.485 47.549,45.485 49.239,47.175 51.575,47.175 52.195,47.795 CN2.34@53.5,47.795 v1(55.34,47.795)
  Bottom Layer w0.12: SB5.2@4.9,48.75 4.9,47.975 5.15,47.725 v1(6.15,47.725) ; v1(27.525,47.7) 30.7,47.7 31.38,47.02 32.712,47.02 33.092,47.4 35.571,47.4 35.846,47.675 v1(35.875,47.675) ; SB40.2@54.225,46.35 55.116,46.35 55.34,46.574 v1(55.34,47.795)
WIFI.PTA_PRI: CN2.42 SB23.2 SB31.2 | length 67.7
  Top Layer w0.12: v1(9.1,52.775) 10.21,51.665 14.04,51.665 14.625,52.25 20.321,52.25 20.551,52.02 24.82,52.02 24.825,52.025 28.096,52.025 30.101,54.03 33.824,54.03 34.695,53.159 34.695,52.53 34.9,52.325 41.275,52.325 42.05,51.55 43.529,51.55 44.021,51.058 44.342,51.058 v1(44.65,50.75) ; v1(43.4,43.925) 44.017,43.925 44.027,43.915 47.546,43.915 49.386,42.075 51.425,42.075 52.065,42.715 CN2.42@53.5,42.715 53.535,42.75 54.65,42.75 54.795,42.895 54.795,43.024 55.076,43.305 55.08,43.305 55.375,43.6 v1(55.375,44.225)
  Bottom Layer w0.12: SB23.2@4.9,54.5 4.9,53.8 5.02,53.68 8.195,53.68 v1(9.1,52.775) ; v1(43.4,43.925) 44.154,43.925 44.905,44.676 44.905,46.161 44.3,46.766 44.3,49.042 44.65,49.392 v1(44.65,50.75) ; SB31.2@54.225,44.225 v1(55.375,44.225)
WIFI.PTA_STAT: CN1.8 SB20.2 SB39.2 | length 29.8
  Top Layer w0.12: v1(3.525,58.225) 3.525,59.332 7.76,63.567 7.76,65.507 8.328,66.075 v1(11.525,66.075) 14.491,66.075 14.641,66.225 17.3,66.225 17.425,66.1 17.425,65.075 17.62,64.88 17.62,64.735 18.05,64.305 CN1.8@19.21,64.305
  Bottom Layer w0.12: v1(3.525,58.225) 3.525,57.359 3.81,57.074 3.81,53.275 4.085,53 SB20.2@4.9,53 ; v1(11.525,66.075) SB39.2@11.525,67.325
pads on no net: B1.NPTH1 B1.NPTH2 CART-1.1 CN1.3 CN1.4 CN1.5 CN1.10 CN1.16 CN1.27 CN2.4 CN2.6 CN2.24 CN2.36 CN3.5 CN3.7 CN3.MT1 CN3.MT2 CN4.5 CN4.7 CN4.MT1 CN4.MT2 CN5.0 CN5.A2 CN5.A3 CN5.A8 CN5.A10 CN5.A11 CN5.B2 CN5.B3 CN5.B8 CN5.B10 CN5.B11 CN6.0 CN6.A2 CN6.A3 CN6.A8 CN6.A10 CN6.A11 CN6.B2 CN6.B3 CN6.B8 CN6.B10 CN6.B11 CN12.0 CN14.0 CN14.1 CN14.2 CN15.7 CN15.11 CN15.12 CN15.13 MIRE-1.1 MIRE-2.1 MIRE-3.1 MIRE-4.1 MIRE-5.1 MIRE-6.1 U6.A1 U6.A2 U6.A3 U6.A4 U6.A5 U6.A8 U6.A9 U6.A11 U6.A12 U6.A13 U6.B1 U6.B2 U6.B3 U6.B4 U6.B5 U6.B6 U6.B7 U6.B8 U6.B9 U6.B10 U6.B11 U6.B12 U6.B13 U6.B15 U6.C2 U6.C3 U6.C12 U6.C13 U6.C14 U6.C15 U6.D1 U6.D2 U6.D3 U6.D7 U6.D8 U6.D9 U6.D11 U6.D13 U6.D14 U6.E1 U6.E2 U6.E3 U6.E4 U6.E12 U6.E13 U6.E14 U6.E15 U6.F1 U6.F2 U6.F4 U6.F14 U6.G4 U6.G10 U6.G12 U6.G14 U6.G15 U6.H2 U6.H3 U6.H4 U6.H12 U6.H14 U6.J3 U6.J4 U6.K1 U6.K2 U6.K3 U6.K12 U6.K13 U6.K14 U6.K15 U6.L1 U6.L12 U6.L13 U6.L14 U6.L15 U6.M2 U6.M3 U6.M4 U6.M7 U6.M9 U6.M12 U6.M13 U6.M14 U6.M15 U6.N2 U6.N4 U6.N6 U6.N7 U6.N11 U6.N15 U6.P2 U6.P4 U6.P5 U6.P6 U6.P7 U6.P8 U6.P9 U6.P10 U6.P11 U6.P12 U6.P13 U6.P14 U6.P15 U6.R2 U6.R3 U6.R6 U6.R7 U6.R8 U6.R9 U6.R10 U6.R11 U6.R12 U11.4 U13.H1 U21.6 U22.16 U22.17 U22.18

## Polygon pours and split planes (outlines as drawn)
5V on Bottom Layer "5V_L04_P-001" (solid, pour order 8): 26.75,53.125 26.75,54.25 28.5,56 30.575,56 30.575,54.925 31.65,53.85 31.65,52.825 28.425,52.825 28.125,53.125
GND on Bottom Layer "GND_L04" (solid, remove dead copper, pour order 19): 0,70 70,70 70,0 0,0
3V6 on Bottom Layer "5V_L04_P-001" (solid, pour order 18): 23.675,53.16 23.675,55.134 23.951,55.41 25.095,55.41 25.095,53.16
5V_VIN on Bottom Layer "5V_VIN_L04" (solid, pour order 11): 16.5,53.75 16,53.75 16,49.75 18,49.75 18.5,49.25 18.5,46 20,46 20,49.25 20.5,49.75 22.5,49.75 22.5,51.5 23,52 23,54.5 22,55.5 16.5,55.5
VIN on Bottom Layer "VIN_L04" (solid, pour order 10): 13.45,44.975 14.2,45.725 16.225,45.725 16.725,46.225 17.7,47.2 17.7,49.225 12.95,49.225 11.625,47.9 11.625,44.975
3V3 on Bottom Layer "3V3_L04_P-001" (solid, pour order 9): 32.25,50.5 32.25,48 36,48 36,48.5 40.5,48.5 40.5,51.5 38,51.5 38,53 36,53 36,54.5 32.25,54.5 32.25,52 30.5,52 30.5,50.5
5V on Bottom Layer "5V_L04" (solid, pour order 6): 10,37.25 8.25,35.5 7.25,35.5 7,35.75 7,37.5 7.75,38.25 10,38.25
VBUS_STLK on Bottom Layer "VBUS_STLK_L01" (solid, pour order 2): 16.9,30.55 18.3,30.55 18.5,30.75 18.5,32.5 17.35,32.5 17.05,32.2 17.05,31.55 16.9,31.4
5V_STLK on Bottom Layer "5V_STLK_L04" (solid, pour order 3): 16.9,29.15 18.1,29.15 18.5,28.75 18.5,27.15 19.2,26.45 19.2,25.95 18.75,25.5 17.25,25.5 16.9,25.85 16.9,28.1
5V_STLK on Signal Layer 1 "5V_STLK_L02" (solid, remove dead copper, pour order 13): 3.75,27.5 17.5,27.5 18.5,26.5 18.5,25.25 18,24.75 4.5,24.75 3.75,25.5
GND on Signal Layer 1 "GND_L02_P021" (solid, remove dead copper, pour order 21): 18.025,24.5 18.475,24.05 18.475,19.025 18.2,18.75 12.975,18.75 11.925,17.7 11.925,11.825 15,8.75 70,8.75 70,0.25 69.75,0 0,0 0,24.5
GND on Signal Layer 1 "GND_L02_P020" (solid, remove dead copper, pour order 20): 51.425,63.325 51.4,63.3 51.4,56.65 51.725,56.325 58.125,56.325 62,52.559 62,44.775 62.95,43.825 66,43.825 66.625,43.2 66.625,39.325 66,38.7 62.675,38.7 62,38.025 62,6.929 70,6.929 70,70 0.64,70 0.35,69.71 0.35,69.275 0.65,68.975 38.325,68.975 40.625,66.675 44.175,66.675 45.1,67.6 47.15,67.6
5V_VIN on Signal Layer 1 "5V_VIN_L02" (solid, remove dead copper, pour order 12): 17.75,28 19,26.75 19,16 22.75,12.25 47.25,12.25 49.75,14.75 49.75,26.75 31,26.75 31,23.5 26.5,19 23.25,19 23.25,33.25 23.25,53.5 22.75,54 20.75,54 17.25,50.5 12.5,50.5 10.25,48.25 10.25,35.5 9.5,34.75 7.25,34.75 6.5,34 6.5,31 6.25,30.75 4.25,30.75 3.75,30.25 3.75,28.5 4.25,28
5V on Signal Layer 1 "5V_L02_P-001" (solid, remove dead copper, pour order 7): 1,60 1,25.75 1.5,25.25 3,25.25 3.5,25.75 3.5,35 3.75,35.25 9.25,35.25 9.75,35.75 9.75,48.75 12,51 17,51 20.5,54.5 23,54.5 23.75,53.75 23.75,19.5 26.5,19.5 30.5,23.5 30.5,56.175 26.675,60
VBAT on Signal Layer 1 "3V3_MCU_L02" (solid, remove dead copper, pour order 14): 13.721,18.475 12.275,17.029 12.25,16.15 12.25,12.5 15.5,9.25 61.5,9.25 61.5,38.55 62.3,39.35 65.725,39.35 66.175,39.8 66.175,42.825 65.7,43.3 62.725,43.3 61.5,44.525 61.5,52.05 57.937,55.613 57.9,55.65 51.575,55.65 50.8,56.425 50.8,62.7 50.425,63.125 47.6,65.95 40.225,65.95 38.475,67.7 33.075,67.7 32.4,68.375 1,68.375 1,60.5 26.675,60.5 31,56.175 31,42.5 42.75,42.5 47.25,38 53,38 57.75,33.25 57.75,13 57,12.25 48,12.25 47.5,11.75 22.5,11.75 18.5,15.75 18.5,18.475
3V3_STLK on Signal Layer 1 "3V3_STLK_L02" (solid, remove dead copper, pour order 4): 45,39.5 47,37.5 52.5,37.5 57.25,32.75 57.25,18.25 57.25,13.25 56.75,12.75 52.25,12.75 50.25,14.75 50.25,26.75 49.75,27.25 31,27.25 31,42 42.5,42
GND on Top Layer "NONET_L-01_P-001" (solid, remove dead copper, pour order 23): 43.282,66.725 42.375,66.725 41.5,67.6 35.6,67.6 35.25,67.95 35.25,70 43.268,70
GND_Audio on Top Layer "NONET_L-01_P-001" (solid, remove dead copper, pour order 22): 41.5,60 41,59.5 37.5,59.5 37,60 37,63 38,64 40.22,64 41.5,62.721
GND on Top Layer "GND_L01" (solid, remove dead copper, pour order 17): 36.485,63.389 36.95,63.854 36.95,69.535 36.485,70 0,70 0,0 70,0 70,70 42.025,70 42.025,59.55 41.35,58.875 37.3,58.875 36.485,59.69
5V on Top Layer "5V_L01" (solid, pour order 16): 25.25,21 25.25,19.225 23.75,19.225 23.75,21
5V on Top Layer "g" (solid, pour order 5): 7,38 8.25,38 8.63,37.62 8.63,35.88 8.25,35.5 6.25,35.5 6.25,36.5 7,37.25
GND on Signal Layer 2 "NONET_L-01_P-001" (solid, remove dead copper, pour order 26): 64.75,64.5 64.75,64.75 62.5,67 46,67 44,69 42.4,69 40.4,67 2.25,67 1.5,66.25 1.5,58.5 0,58.5 0,70 65.369,70 65.75,69.619 65.75,64.5
GND_Audio on Signal Layer 2 "NONET_L-01_P-001" (solid, remove dead copper, pour order 24): 63,65.75 62.25,66.5 45.875,66.5 43.875,68.5 42.5,68.5 40.5,66.5 2.5,66.5 2,66 2,59.5 2.5,59 31,59 34.5,55.5 46,55.5 52,61.5 61.175,61.5 63,63.325
GND on Signal Layer 2 "GND_L01_P-001" (solid, remove dead copper, pour order 0): 70,70 63.75,70 63.75,63.45 61.3,61 52.25,61 46.25,55 34.25,55 30.75,58.5 2.25,58.5 0.97,59.78 0,59.78 0,48.15 0,0 70,0

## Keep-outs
Keep-Out Layer:
  region: 46,4.5 46,2.5 52.5,2.5 52.5,4.5
  rectangle: 46.25,2.625 52.375,4.375

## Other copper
Top Layer:
  pour cut-out: 39.08,40.895 39.075,40.89 39.075,39.935 38.395,39.255 38.395,38.295 39.298,38.295 39.352,38.241 39.352,35.97 39.232,35.85 38.35,35.85 38.28,35.92 38.28,36.83 37.73,36.83 37.605,36.705 36.02,36.705 36.025,36.7 36.025,36 35.925,35.9 34.602,35.9 34.505,35.803 34.505,34.83 34.149,34.474 33.557,34.474 32.624,35.407 32.498,35.282 32.498,33.752 33.18,33.07 33.505,33.07 33.505,31.745 33.625,31.625 34.624,31.625 35.549,32.55 36.5,32.55 36.925,32.975 36.925,33.7 37.025,33.8 37.925,33.8 38.025,33.7 38.025,33.1 38.6,32.525 39.475,32.525 39.475,33.35 40.025,33.9 42.1,33.9 42.3,34.1 42.3,34.8 42.15,34.95 41.775,34.95 41.6,35.125 41.6,36.525 41.73,36.655 41.73,37.53 41.925,37.725 42.25,37.725 42.25,39.05 39.5,41.8 39.075,41.8
  pour cut-out: 30.62,39.255 30.425,39.45 29.981,39.45 29.899,39.368 29.85,39.416 29.85,39.75 30.225,40.125 32.6,40.125 32.957,39.768 32.957,38.125 32.95,38.125 32.6,37.775 32.55,37.825 32.225,37.825 32.225,38.107 32.243,38.125 32.073,38.295 30.62,38.295
  pour cut-out: 35.287,39.325 34.375,39.325 34.375,40.15 34.63,40.405 35.47,40.405 35.47,39.507
  pour cut-out: 43.6,68.2 43.4,68.4 40.75,68.4 40.325,67.975 40.325,67 40.55,66.775 43.35,66.775 43.6,67.025
  pour cut-out: 68.45,21.22 66.8,21.22 66.775,21.195 66.775,20.25 66.9,20.125 68.45,20.125
  pour cut-out: 54.52,46.991 54.6,46.911 54.6,44.625 53.58,43.605 48.895,43.605 48.475,44.025 48.475,46.75 48.716,46.991
  pour cut-out: 31.43,53.366 31.43,51.87 32.12,51.18 33.905,51.18 34.025,51.3 34.025,52.875 33.975,52.875 33.475,53.375
  pour cut-out: 20.23,46.916 20.23,39.833 21.562,38.5 21.53,38.468 21.53,37.03 15.14,37.03 15.11,37.06 15.11,48.609 19.866,48.609 20.225,48.25
  pour cut-out: 17.23,55.91 17.245,55.925 17.474,55.925 17.809,55.59 17.8,55.581 17.8,54.351 18.501,53.65 20.23,53.65 20.23,52.745 19.86,52.375 17.225,52.375
  pour cut-out: 20.75,58.225 20.575,58.4 18.31,58.4 17.6,57.69 17.6,56.425 17.835,56.19 20.49,56.19 20.75,56.45
  pour cut-out: 18.19,61.27 17.23,61.27 17.23,58.73 12.62,58.73 12.325,59.025 12.325,62.45 12.575,62.7 17.65,62.7 18.2,62.15
  pour cut-out: 1.1,38 1.129,38.029 5.156,38.029 5.824,37.361 5.824,31.509 5.515,31.2 5.515,28.16 5.815,27.86 5.815,25.77 1.43,25.77 1.075,26.125
  pour cut-out: 3.375,26.725 3.285,26.815 1.176,26.815 1.176,23.834 1.26,23.75 3.725,23.75 3.775,23.8 3.775,26.65 3.7,26.725
  pour cut-out: 12.75,7.15 11.475,7.15 11.1,6.775 11.1,5.675 11.35,5.425 12.325,5.425 12.775,5.875
  pour cut-out: 8.547,12.3 1.453,12.3 1.453,3.7 8.547,3.7 8.547,4.744 8.875,5.072 10.222,5.072 10.4,5.25 10.4,8.717 9.842,9.275 9.325,9.275 9.225,9.175 9.225,8.5 9.075,8.35 5.628,8.35 4.853,7.575 4.375,7.575 4.375,9.05 5.025,9.7 8.55,9.7
  pour cut-out: 18.825,12.15 18.384,12.591 14.716,12.591 13.725,11.6 13.725,5.594 14.561,4.759 17.209,4.759 18.5,6.05 18.5,7.35 18.525,7.35 18.825,7.65
  pour cut-out: 30.155,2.675 30.025,2.675 30.025,3.745 28.375,3.745 28.295,3.665 28.295,1.795 30.025,1.795 30.155,1.925
  pour cut-out: 43.32,8.91 42.722,9.509 41.484,9.509 41.23,9.255 41.23,8.375 43.32,8.375
  pour cut-out: 56.651,63.568 56.638,63.568 55.735,64.471 52.846,64.471 52.35,63.975 51.7,63.975 51.52,64.155 51.52,67.73 50.95,68.3 49.395,68.3 47.5,66.405 47.5,60.6 55.95,60.6 56.65,61.3
  text "1" at 46.514,2.857 h2
Signal Layer 1:
  text "2" at 47.949,2.857 h2
Signal Layer 2:
  text "3" at 49.581,2.868 h2
Bottom Layer:
  pour cut-out: 36.57,56.655 36.81,56.415 36.81,56.185 37.94,56.185 38.032,56.093 40.132,56.093 40.639,55.586 40.639,54.026 40.639,53.511 40.95,53.2 42.525,53.2 42.686,53.361 42.686,57.439 42.35,57.775 36.8,57.775 36.57,57.545
  pour cut-out: 44.578,51.872 44.575,51.869 44.575,49.317 43.958,48.7 40.575,48.7 40.575,50.825 41.65,51.9
  pour cut-out: 44.975,53.875 44.943,53.843 43.93,53.843 43.505,54.268 43.505,56.48 44.47,56.48 44.975,55.975
  pour cut-out: 42.455,57.67 42.415,57.71 41.085,57.71 41.02,57.775 39.126,57.775 38.851,57.5 38.025,57.5 37.94,57.585 36.34,57.585 35.425,58.5 35.425,59.5 35.625,59.7 42,59.7 42.475,59.225
  pour cut-out: 44.32,67.18 43.429,68.071 42.596,68.071 40.85,66.325 40.85,65.025 40.5,64.675 43.575,64.675 43.75,64.85 43.84,64.85 44.32,65.33
  pour cut-out: 50.525,62.825 50.475,62.875 49.651,62.875 49.503,62.727 49.503,54.15 48.775,54.15 48.055,54.87 48.055,59.973 47.705,60.323 47.705,63.18 48.675,64.15 48.7,64.125 50.5,64.125
  pour cut-out: 55.05,67.089 54.039,67.089 53.95,67 51.42,67 51.42,66.184 54.784,66.184 55.05,66.45
  pour cut-out: 57.1,47.575 57.1,47.875 55.9,49.075 51.275,49.075 51.025,48.825 51.025,44.475 51.775,43.725 57.241,43.725 57.425,43.909 57.425,47.375
  text "4" at 51.182,2.859 h2

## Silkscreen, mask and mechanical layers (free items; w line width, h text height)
Top Overlay:
  lines w0.12: 14.25,63 14.625,62.625 14.625,59.5 14.875,59.25 ; 14.25,64.625 14.625,64.25 14.625,63 14.875,62.75 14.875,60.75 15,60.625 ; 14.375,65.75 14.875,65.375 14.875,63.25 15,63.125 ; 54.562,63.625 54.875,64.875 55.125,65.125 ; 54.625,61.188 55.125,60.063
  text "PH3" at 11.679,65.526 h1.5
  text "PD5" at 46.859,64.903 h1.5
  text "PD8" at 55.313,64.588 h1.5
  text "PA13" at 11.008,64.276 h1.5
  text "PA15" at 20.625,63.901 h1.5
  text "PB2" at 46.952,63.83 h1.5
  text "PA14" at 11.012,63.018 h1.5
  text "PB1" at 47.127,62.768 h1.5
  text "PB10" at 46.198,61.713 h1.5
  text "PA9" at 46.939,60.088 h1.5
  text "PB3" at 55.286,59.531 h1.5
  text "PC3" at 46.929,58.77 h1.5
  text "AUDIO_IN" at 2,58.25 h1.5 r90
  text "PE1" at 12.439,56.268 h1.5
  text "PB9" at 46.752,54.963 h1.5
  text "PA15" at 54.911,54.906 h1.5
  text "PE2" at 12.264,54.893 h1.5
  text "AUDIO_OUT" at 68.225,54.425 h1.5 r90
  text "PB11" at 46.193,53.643 h1.5
  text "PE3" at 12.254,53.526 h1.5
  text "PA4" at 20.625,53.519 h1.5
  text "PA10" at 46.011,52.401 h1.5
  text "PA6" at 20.625,52.276 h1.5
  text "PA7" at 54.848,51.15 h1.5
  text "PD14" at 45.937,51.143 h1.5
  text "PC4" at 12.183,49.895 h1.5
  text "PB0" at 46.757,49.901 h1.5
  text "PD9" at 54.848,49.844 h1.5
  text "PC14" at 11.437,47.395 h1.5
  text "PB15" at 54.848,47.344 h1.5
  text "PC15" at 11.426,46.019 h1.5
  text "PA2" at 20.625,46.018 h1.5
  text "PB14" at 46.012,45.768 h1.5
  text "PA3" at 46.754,44.651 h1.5
  text "PA1" at 20.625,44.643 h1.5
  text "PC5" at 54.875,43.52 h1.5
  text "PB13" at 46.008,43.463 h1.5
  text "PA5" at 20.625,42.278 h1.5
  text "PE0" at 46.757,42.213 h1.5
  text "PB4" at 54.848,42.213 h1.5
  text "PWR" at 1.27,41.514 h1.5
  text "PA0" at 20.625,41.026 h1.5
  text "PA12" at 46.018,40.955 h1.5
  text "PA8" at 12.127,39.776 h1.5
  text "PA11" at 46.193,39.705 h1.5
  text "PC13" at 54.848,39.713 h1.5
  text "PB8" at 54.848,38.406 h1.5
  text "PB12" at 11.393,38.393 h1.5
  text "5V_USB_MCU" at 6.5,36.248 h1.4
  text "VBUS_STLK" at 6.476,34.248 h1.4
  text "5V_EXT" at 6.425,31.273 h1.4
  text "5V_VIN" at 6.5,29.073 h1.4
  text "J" at 13.525,26.725 h12
  text "5V_STLK" at 6.475,26.273 h1.4
  text "ARD" at 69.7,25.817 h1.5 r90
  text "RESERVED" at 51.384,25.375 h1.5 r90
  text "MB2143A" at 13.35,25.325 h2
  text "USB" at 10.15,21.894 h1.5
  text "PW_ST" at 51.575,18.148 h1.4
  text "STLK" at 52.3,9.44 h1.4
  text "RST" at 22.275,1.516 h1.5
  text "MIPI10" at 2.875,0.441 h1.5
  text "TAG" at 14.725,0.366 h1.5
Bottom Overlay:
  lines w0.12: 60.7,58.95 61.325,59.6 61.775,59.6
  text "SB18-17" at 39.625,64.625 h1.3 r270
  text "A5" at 8.806,62.825 h1.5
  text "D0 Rx" at 65.4,62.75 h1.4
  text "D1 Tx" at 65.35,60.5 h1.4
  text "A4" at 8.528,60.2 h1.3
  text "D2" at 63.7,59.125 h1.4
  text "A3" at 8.807,57.666 h1.5
  text "A2" at 8.311,55.125 h1.3
  text "D3 / PWM" at 64.869,54.575 h1.4
  text "D4" at 63.7,52.625 h1.4
  text "A1" at 8.807,52.575 h1.5
  text "A0" at 8.318,50.114 h1.3
  text "D5 / PWM" at 64.869,49.6 h1.4
  text "D6 / PWM" at 64.894,46.975 h1.4
  text "D7" at 63.475,45.075 h1.4
  text "VIN" at 8.805,44.975 h1.5
  text "GND" at 7.25,41.5 h1.5 r270
  text "D8" at 63.7,40.9 h1.4
  text "GND" at 9.3,39.9 h1.5
  text "D9 PWM" at 67.289,38.891 h1.5
  text "5V" at 8.2,37.4 h1.5
  text "D10 CS / PWM" at 70.266,36.05 h1.5
  text "3V3" at 8.953,34.766 h1.5
  text "D11  / MOSI / PWM" at 64.25,32.325 h1.3
  text "NRST" at 8.3,32.315 h1.4
  text "D12 MISO" at 68.1,30.816 h1.5
  text "IOREF" at 9.3,29.716 h1.5
  text "D13 / SCK" at 64.55,27.625 h1.4
  text "NC" at 8.2,27.216 h1.5
  text "GND" at 64.9,25.625 h1.4
  text "VREFP" at 66.075,23.15 h1.4
  text "D14 / SDA" at 64.693,20.1 h1.4
  text "H" at 23.725,19.35 h10
  text "E" at 7.85,18.5 h9
  text "D15 / SCL" at 64.3,17.4 h1.4
  text "I" at 11.675,3.5 h10
  text "G" at 65.35,2.5 h7
  text "UK / CA" at 23.9,2.25 h3.5
  text "F" at 57.425,2.25 h8
Top Solder:
  rectangle: 46.25,2.625 52.375,4.375
Bottom Solder:
  rectangle: 46.25,2.625 52.375,4.375
M1-Board Shape:
  lines w0.1: 1.5,70 1,70 ccw(c1,69) 0,69 0,1 ccw(c1,1) 1,0 69,0 ccw(c69,1) 70,1 70,69 ccw(c69,69) 69,70 1.5,70 ; 1.5,70 1.5,70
